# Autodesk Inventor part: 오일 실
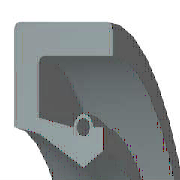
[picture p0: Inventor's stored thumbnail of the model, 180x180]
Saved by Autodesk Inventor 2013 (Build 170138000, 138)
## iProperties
IsCustomPart: 0
Created: 2016-05
Part Number: 오일 실
Material: 고무
Description: 오일-실
Document SubType Name: Modeling
Standard: KS B 2804
Designer: mduedu
Standards Organization: KS
Language: ko-KR
Size Designation: S - 17 30 8
Categories: <MemberInstance><Categories><Category DisplayName="샤프트 부품" InternalName="7f7aeb1f-a693-4053-b835-cee3144e0d98" Mnemonic="SHFT"><Category DisplayName="실링" Intern
Density: 0.93 g/cm^3
Author: mduedu
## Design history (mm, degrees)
revolve "본체" stored, may be unused: angle "d17" = 90 deg
revolve "스프링1" stored, may be unused: angle "d18" = 90 deg
body "Solid1"
sketch "스케치1"
  geometry: L1 (0, 15)-(8, 15); L2 (8, 15)-(8, 13.75); L3 (8, 13.75)-(1.75, 13.75); L4 (0, 15)-(0, 10.6); L5 (0, 10.6)-(1.75, 10.25); L6 (1.75, 10.25)-(4.9, 8.5); L7 (4.9, 8.5)-(0, 8.5); L8 (6.3, 9.375)-(6.3, 10.6); L9 (0, 0)-(9.586, 0) reference; L10 (4.9, 8.5)-(6.3, 9.375); L11 (0, 18)-(0, -3) reference; L12 (-1.917, 0)-(11.503, 0) reference; L13 (4.2, 10.6)-(1.75, 11.09); L14 (1.75, 11.09)-(1.75, 13.75); L15 (6.3, 10.6)-(5.6, 10.6); C1 r 0.455 at (4.9, 10.6); A1 r 0.7 centre (4.9, 10.6) between (5.6, 10.6) and (4.2, 10.6)
  constraints: 26 end point, 5 horizontal alignment, 4 perpendicular, 2 centre point, 2 collinear, 2 horizontal, 2 parallel, 2 point on circle, 2 point on line, 2 vertical alignment, 1 coincident
  dimensions: "d0" = 30 diameter of L1 L9 (= SD2); "d1" = 18.75 diameter of L8.start L9 (= ABDM); "d2" = 1.25 distance of L1.end L2.end (computed from SD); "d3" = 0.91 diameter of C1 (= SPDI); "d4" = 1.4 diameter of A1 (= SPDA); "d5" = 17 diameter of L6.end L9 (= NND); "d6" = 20.5 diameter of L5.end L9 (= TKDM); "d7" = 21.2 diameter of L4.end L9 (= HLDM); "d8" = 4.9 distance from line of C1.centre L4 (= SPDST); "d9" = 6.3 distance between parallel lines of L8 L4 (= SDI); "d10" = 8 distance between parallel lines of L2 L4 (= SWDT); "d12" = 1.75 distance between parallel lines of L14 L4 (= SD)
fillet "모깎기1" dims "d11" = 0.3 (= RR)
other parameters: "SD2" = 30 [user parameter; used in 1 equation term], "SWDT" = 8 [user parameter; used in 1 equation term], "RR" = 0.3 [user parameter; used in 1 equation term], "SD" = 1.75 [user parameter; used in 2 equation terms], "NND" = 17 [user parameter; used in 1 equation term], "SPDA" = 1.4 [user parameter; used in 1 equation term], "SPDI" = 0.91 [user parameter; used in 1 equation term], "TKDM" = 20.5 [user parameter; used in 1 equation term], "HLDM" = 21.2 [user parameter; used in 1 equation term], "ABDM" = 18.75 [user parameter; used in 1 equation term], "SDI" = 6.3 [user parameter; used in 1 equation term], "SPDST" = 4.9 [user parameter; used in 1 equation term], "d13" = 0, "d14" = 0, "d15" = 0, "LAB" = 0.35 [user parameter]
